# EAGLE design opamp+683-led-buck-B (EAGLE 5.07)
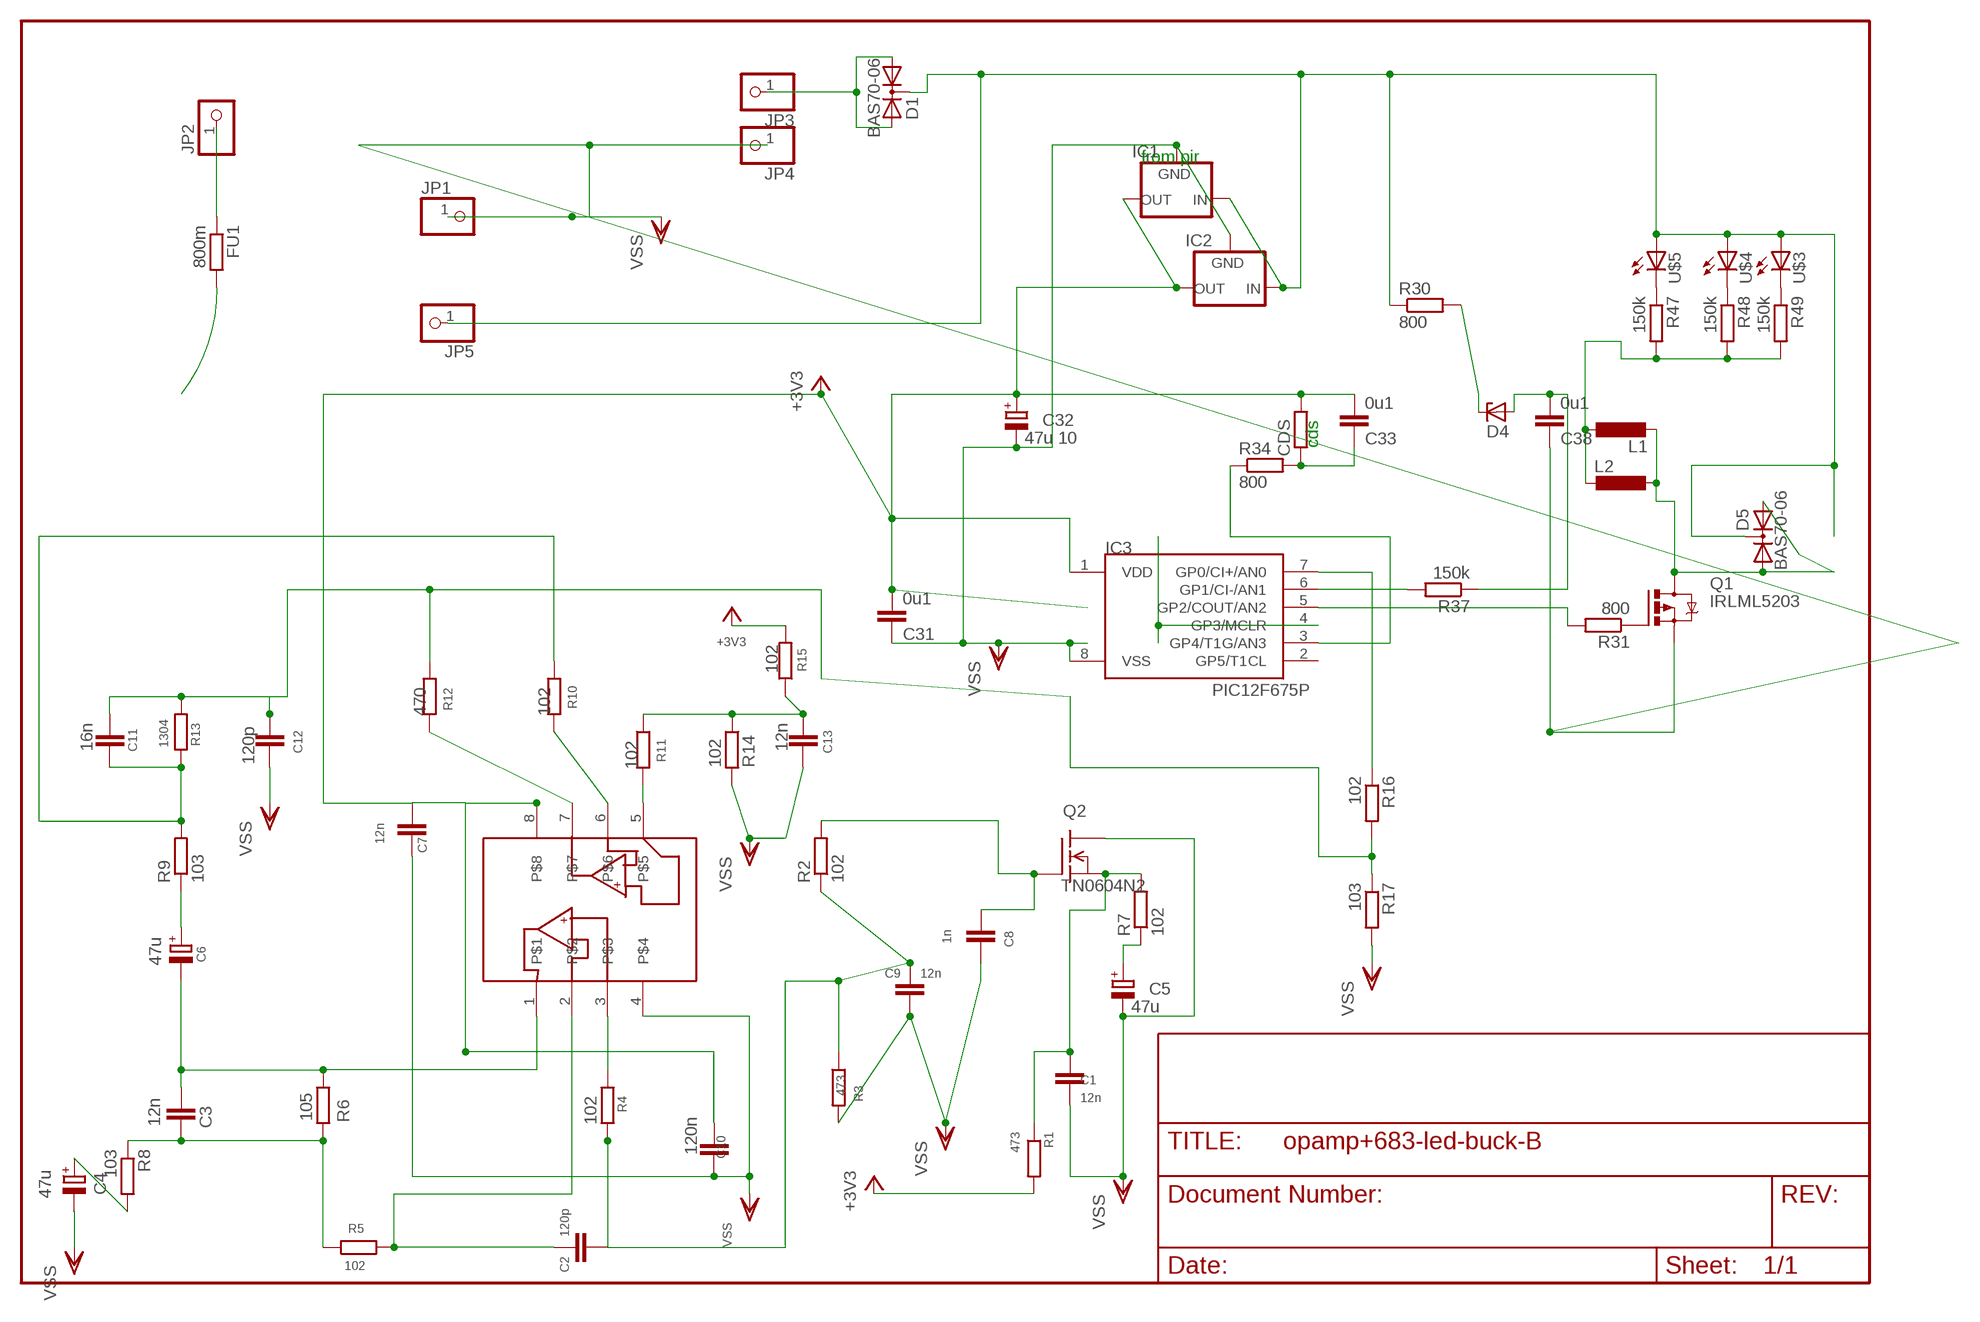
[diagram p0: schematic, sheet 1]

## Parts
C1  12n  C-EUC0805  [C0805]
C2  120p  C-EUC0805  [C0805]
C3  12n  C-EUC0805  [C0805]
C4  47u  CPOL-EUE2.5-5  [E2,5-5]
C5  47u  CPOL-EUE2.5-5  [E2,5-5]
C6  47u  CPOL-EUE2.5-5  [E2,5-5]
C7  12n  C-EUC0805  [C0805]
C8  1n  C-EUC0805  [C0805]
C9  12n  C-EUC0805  [C0805]
C10  120n  C-EUC0805  [C0805]
C11  16n  C-EUC0805  [C0805]
C12  120p  C-EUC0805  [C0805]
C13  12n  C-EUC0805  [C0805]
C31  0u1  C-EUC1206  [C1206]
C32  47u 10  CPOL-EUE2.5-5  [E2,5-5]
C33  0u1  C-EUC1206  [C1206]
C38  0u1  C-EUC0805  [C0805]
CDS  R-EU_0207/5V  [0207/5V]
D1  BAS70-06  [SOT23]
D4  ZENER-DIODESOT23  [SOT23]
D5  BAS70-06  [SOT23]
FU1  800m  R-EU_0204/5  [0204/5]
IC1  XC63FPT  [TO92]
IC2  XC63FPP  [SOT89R]
IC3  PIC12F675P  [DIL8]
JP1  PINHD-1X1  [1X01]
JP2  PINHD-1X1  [1X01]
JP3  PINHD-1X1  [1X01]
JP4  PINHD-1X1  [1X01]
JP5  PINHD-1X1  [1X01]
L1  L-EUL5650M  [L5650M]
L2  L-EU0207/7  [0207/7]
Q1  IRLML5203  [MICRO3]
Q2  TN0604N2  [TO-39]
R1  473  R-EU_R0805  [R0805]
R2  102  R-EU_R0805  [R0805]
R3  473  R-EU_R0805  [R0805]
R4  102  R-EU_R0805  [R0805]
R5  102  R-EU_R0805  [R0805]
R6  105  R-EU_R0805  [R0805]
R7  102  R-EU_R0805  [R0805]
R8  103  R-EU_R0805  [R0805]
R9  103  R-EU_R0805  [R0805]
R10  102  R-EU_R0805  [R0805]
R11  102  R-EU_R0805  [R0805]
R12  470  R-EU_R0805  [R0805]
R13  1304  R-EU_R0805  [R0805]
R14  102  R-EU_R0805  [R0805]
R15  102  R-EU_R0805  [R0805]
R16  102  R-EU_R0805  [R0805]
R17  103  R-EU_R1206  [R1206]
R30  800  R-EU_R0805  [R0805]
R31  800  R-EU_R0805  [R0805]
R34  800  R-EU_0617/22  [0617/22]
R37  150k  R-EU_0207/12  [0207/12]
R47  150k  R-EU_R1206  [R1206]
R48  150k  R-EU_R1206  [R1206]
R49  150k  R-EU_R1206  [R1206]
U$1  MCP6042SOIC  [SO-08]
U$3  LED5MM  [LED5MM]
U$4  LED5MM  [LED5MM]
U$5  LED5MM  [LED5MM]

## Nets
+3V3: C7.1 C10.1 C31.2 C32.+ C33.2 CDS.2 IC1.3(OUT) IC2.3(OUT) IC3.1(VDD) R1.2 R15.2 U$1.8
N$1: D1.1(A1) D1.2(A2) JP3.1
N$4: FU1.1 JP2.1
N$6: D4.3(C) R30.2
N$7: D1.3(C) D5.3(C) IC1.2(IN) IC2.2(IN) JP5.1 R30.1 U$3.A U$4.A U$5.A
N$9: FU1.2
N$10: Q1.1(G) R31.1
N$11: C5.+ R7.1
N$12: IC3.4(GP3/MCLR)
N$13: IC3.6(GP1/CI-/AN1) R37.2
N$14: IC3.5(GP2/COUT/AN2) R31.2
N$19: R4.1 U$1.3
N$21: IC3.3(GP4/T1G/AN3) R34.1
N$22: L1.1 L2.2 R47.2 R48.2 R49.2
N$23: C33.1 CDS.1 R34.2
N$24: C2.1 R5.2 U$1.2
N$25: C3.2 R5.1 R6.2 R8.1
N$26: D5.1(A1) D5.2(A2) L1.2 L2.1 Q1.3(D)
N$27: C4.+ R8.2
N$28: C11.2 R9.2 R10.1 R13.2
N$29: IC3.7(GP0/CI+/AN0) R16.1
N$30: C3.1 C6.- R6.1 U$1.1
N$31: R10.2 U$1.6
N$32: C11.1 C12.2 R12.1 R13.1 R16.2 R17.1
N$34: C38.2 D4.1(A) R37.1
N$35: C6.+ R9.1
N$36: R12.2 U$1.7
N$38: R47.1 U$5.K(C)
N$39: R11.2 U$1.5
N$40: C13.1 R11.1 R14.1 R15.1
N$42: C1.1 Q2.1(S) R1.1 R7.2
N$46: C8.1 Q2.2(G) R2.2
N$52: C2.2 C9.1 R2.1 R3.1 R4.2
N$54: R48.1 U$4.K(C)
N$55: R49.1 U$3.K(C)
VSS: C1.2 C4.- C5.- C7.2 C8.2 C9.2 C10.2 C12.1 C13.2 C31.1 C32.- C38.1 IC1.1(GND) IC2.1(GND) IC3.8(VSS) JP1.1 JP4.1 Q1.2(S) Q2.3(D) R3.2 R14.2 R17.2 U$1.4
Unconnected: IC3.2(GP5/T1CL)

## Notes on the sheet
- from pir
- cds

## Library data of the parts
C1-C3 C7-C13 = rcl-2:C-EU: CAPACITOR, European symbol
C4-C6 C32 = rcl:CPOL-EU: POLARIZED CAPACITOR, European symbol
C31 C33 C38 = rcl:C-EU: CAPACITOR, European symbol
CDS = rcl(2):R-EU_: RESISTOR, European symbol
D1 D5 = diode-1:BAS70-06: Silicon Schottky Diodes General-purpose diode for high-speed switching
D4 = diode-1:ZENER-DIODE: Z-Diode
FU1 R30 R31 R34 R37 R47-R49 = rcl:R-EU_: RESISTOR, European symbol
IC1 IC2 = v-reg:XC63FP: Positiv Voltage Regulators www.torex.co.jp/english/product/pro02/pdf/0201_xc62fp.pdf
IC3 = microchip-3:PIC12F6*: uPC nW 1k Program Flash memory 2x Timer Comparator 10b A/D converter/ 4xIN
JP1-JP5 = pinhead:PINHD-1X1: PIN HEADER
L1 = rcl-2:L-EU: INDUCTOR, European symbol
L2 = rcl:L-EU: INDUCTOR, European symbol
Q1 = transistor-power:IRLML5203: HEXFET P-Channel Power MOSFET
Q2 = transistor-fet:TN0604N2: N-Channel Enhancement MOSFET 40V; 4A; 0,85Ohm
R1-R17 = rcl-2:R-EU_: RESISTOR, European symbol
U$1 = microchip-3:MCP6042
U$3-U$5 = led(3):LED: LED

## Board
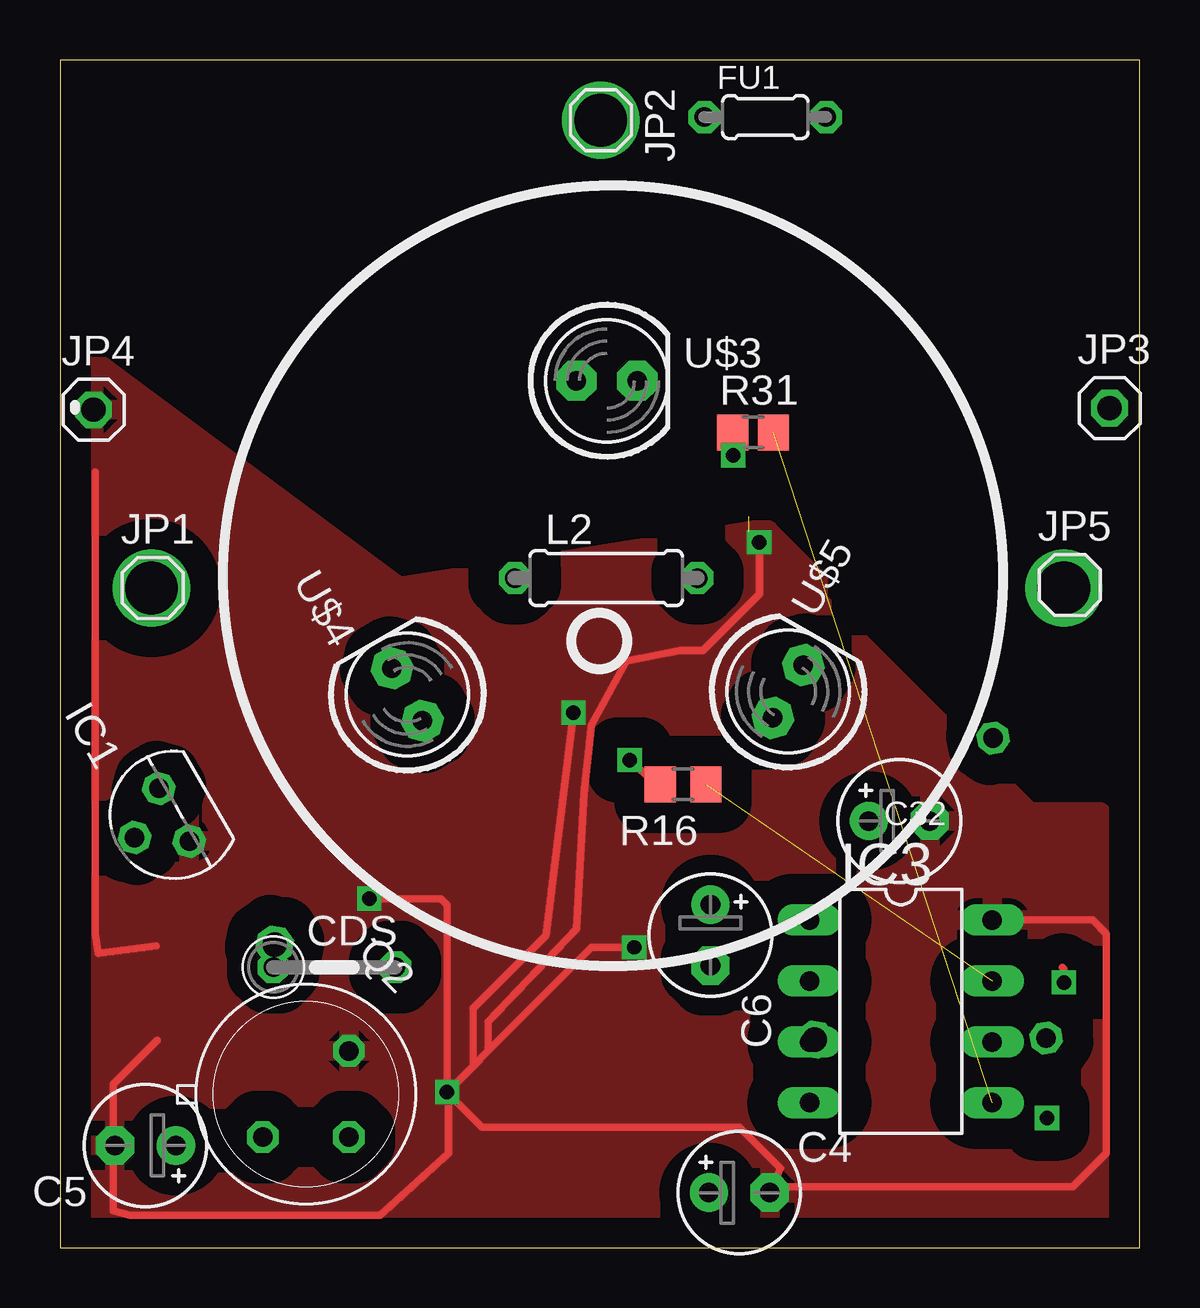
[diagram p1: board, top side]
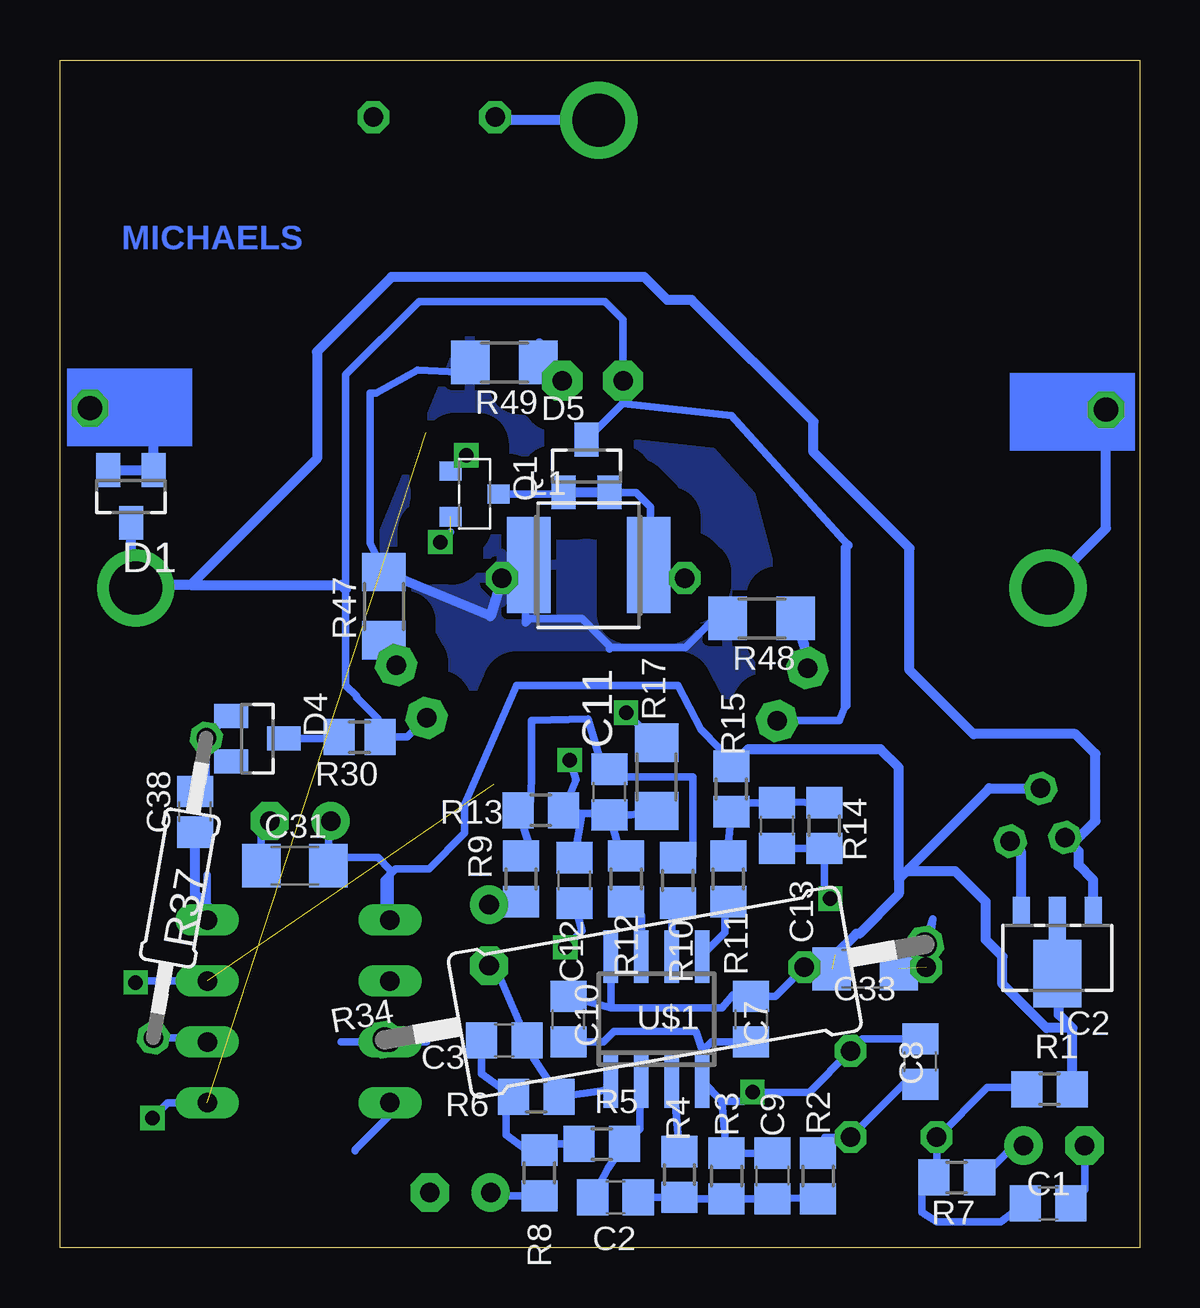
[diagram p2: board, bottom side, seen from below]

Size 45 x 49.5 mm. Coordinates in mm from the lower left corner, seen from the top.
Outline: 0,0 45,0 45,49.5 0,49.5 0,0
Copper layers (1*16): Top 0.035mm / dielectric 1.5mm / Bottom 0.035mm
Design rules "default": minimum track width 10mil, minimum drill 24mil, track to track 8mil, track to pad 8mil, pad to pad 8mil, via to via 8mil, smd to smd 8mil, copper to edge 40mil, drill to drill 8mil, minimum pad ring 10mil, minimum via ring 8mil, stop-mask expansion 4mil, vias tented up to drill 0mil, thermal gap 10mil

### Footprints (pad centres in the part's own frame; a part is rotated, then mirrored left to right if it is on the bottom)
C0805 = smd 1.3 x 1.5: 1 -0.95,0; 2 0.95,0
E2,5-5 = drill 0.813 pad 1.6 round: + -1.27,0 | drill 0.813 pad 1.6 octagon: - 1.27,0
C1206 = smd 1.6 x 1.8: 1 -1.4,0; 2 1.4,0
C0805' = smd 1.3 x 1.5: 1 -0.85,0; 2 0.85,0
0207/5V = drill 0.813 octagon: 1 -2.54,0; 2 2.54,0
SOT23 = smd 1 x 1.4: 1 -0.95,-1.1; 2 0.95,-1.1; 3 0,1.1
0204/5 = drill 0.813 octagon: 1 -2.54,0; 2 2.54,0
TO92 = drill 0.813 octagon: 1 -1.27,0; 2 0,1.905; 3 1.27,0
SOT89R = smd 0.7 x 1.1: 1 1.5,-1.75; 2 -1.5,-1.75 | smd 0.7 x 1.8: 3 0,-1.4 | smd 2 x 2.8: 4 0,0.9
DIL8 = drill 0.813 long: 1 -3.81,-3.81; 2 -1.27,-3.81; 3 1.27,-3.81; 4 3.81,-3.81; 5 3.81,3.81; 6 1.27,3.81; 7 -1.27,3.81; 8 -3.81,3.81
1X01 = drill 1.016 octagon: 1 0,0
L5650M = smd 1.8 x 4: 1 -2.5,0; 2 2.5,0
0207/7 = drill 0.813 octagon: 1 -3.81,0; 2 3.81,0
MICRO3 = smd 0.8 x 0.9: 1 -0.95,-1; 2 0.95,-1; 3 0,1
TO-39 = drill 0.813 octagon: 1 0,-2.54; 2 2.54,0; 3 0,2.54
R0805 = smd 1.3 x 1.5: 1 -0.95,0; 2 0.95,0
R1206 = smd 1.6 x 1.803: 1 -1.422,0; 2 1.422,0
R0805' = smd 1.3 x 1.5: 1 -0.85,0; 2 0.85,0
0617/22 = drill 1.016 octagon: 1 -11.43,0; 2 11.43,0
0207/12 = drill 0.813 octagon: 1 -6.35,0; 2 6.35,0
SO-08 = smd 0.6 x 2.2: 1 -1.905,-2.6; 2 -0.635,-2.6; 3 0.635,-2.6; 4 1.905,-2.6; 5 1.905,2.6; 6 0.635,2.6; 7 -0.635,2.6; 8 -1.905,2.6
LED5MM = drill 0.813 pad 1.676 octagon: A -1.27,0; K 1.27,0

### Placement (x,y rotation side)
C1  3.81,1.84 0 bottom
C2  21.84,2.1 0 bottom
C3  26.48,8.64 180 bottom
C4  28.32,2.29 0 top
C5  3.56,4.25 180 top
C6  27.11,13.02 270 top
C7  16.19,9.53 270 bottom
C8  9.14,7.75 90 bottom
C9  15.3,2.98 90 bottom
C10  23.81,9.53 270 bottom
C11  22.1,18.99 90 bottom
C12  23.56,15.3 90 bottom
C13  15.11,17.59 270 bottom
C31  35.21,15.92 0 bottom
C32  34.99,17.78 0 top
C33  11.43,11.62 180 bottom
C38  0u1  [C0805']  39.37,18.16 90 bottom
CDS  11.43,11.68 0 top
D1  42.04,31.31 180 bottom
D4  36.77,21.21 270 bottom
D5  23.05,32.58 0 bottom
FU1  29.4,47.12 0 top
IC1  4.76,18.04 120 top
IC2  3.43,12.32 180 bottom
IC3  35.05,9.84 270 top
JP1  3.87,27.5 0 top
JP2  22.54,46.99 270 top
JP3  43.75,34.99 0 top
JP4  1.4,34.92 0 top
JP5  42.1,27.62 0 top
L1  22.96,28.44 0 bottom
L2  22.77,27.91 0 top
Q1  27.72,31.41 270 bottom
Q2  10.25,6.4 315 top
R1  3.75,6.6 0 bottom
R2  13.4,2.98 90 bottom
R3  17.21,2.98 90 bottom
R4  19.18,3.05 270 bottom
R5  22.42,4.32 0 bottom
R6  25.15,6.29 180 bottom
R7  7.62,2.92 180 bottom
R8  25.02,3.11 270 bottom
R9  25.78,15.37 90 bottom
R10  19.24,15.3 270 bottom
R11  17.14,15.37 270 bottom
R12  21.4,15.37 270 bottom
R13  24.96,18.22 180 bottom
R14  13.14,17.59 270 bottom
R15  17.02,19.11 90 bottom
R16  25.97,19.3 180 top
R17  20.13,19.62 90 bottom
R30  800  [R0805']  32.51,21.27 180 bottom
R31  800  [R0805']  28.89,33.97 0 top
R34  20.2,10.64 10 bottom
R37  40.01,14.99 260 bottom
R47  31.5,26.73 90 bottom
R48  15.75,26.23 180 bottom
R49  26.48,36.89 180 bottom
U$1  20.13,9.53 0 bottom
U$3  22.8,36.13 0 top
U$4  14.48,23.05 120 top
U$5  30.35,23.18 60 top

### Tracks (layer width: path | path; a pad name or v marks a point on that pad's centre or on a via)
+3V3  (1 unrouted)
  Bottom 0.305: 22.04,10 17.4,10 16.96,10.54 C7.1 15.18,10.47 CDS.2 | 22.04,10 C10.1 | 22.04,10 U$1.8 | C32.+ 33.81,17.69 C31.2 33.47,16.26 31.75,16.26 31.24,15.75 IC3.1 31.5,13.91 31.5,15.3 31.01,15.79 29.62,15.79 28.13,17.27 28.13,18.48 25.97,23.43 19.24,23.43 18.29,21.59 17.53,20.83 R15.2
  Bottom 0.406: R1.2 2.8,9.15 | 2.8,9.15 3.37,9.72 3.37,13.65 IC2.3 | IC1.3 6.26,19.14 9.68,15.72 | 9.68,15.72 10.03,15.37 | 10.03,15.37 10.03,14.73 11.68,13.08 11.81,13.08 12.7,12.19 13.46,12.19 CDS.2 | 10.03,15.37 10.03,20 10.79,20.77 16.32,20.77 R15.2 | 2.8,9.15 3.88,9.15 5.71,10.99 5.71,12.13 6.41,12.83 6.41,14.41 7.68,15.68 9.65,15.68 9.68,15.72
N$1
  Bottom 0.406: JP3.1 43.62,34.86 42.48,34.86 41.09,33.47 D1.1 D1.2
N$2  (via drill 2.2)
  other vias: 3.81,27.5
N$3  (via drill 2.2)
  other vias: 41.85,27.5
N$4
  Bottom 0.406: JP2.1 26.73,46.99 FU1.1
N$5  (via drill 2.2)
  other vias: 22.54,46.99
N$6
  Bottom 0.305: D4.3 33.42,21.21 R30.2
N$7
  Bottom 0.305: U$4.A 15.09,21.97 12.51,21.97 12.26,22.6 | U$5.A 30.52,21.27 R30.1 31.75,21.36 31.75,22.04 32.64,22.92 32.64,22.99 33.08,23.43 33.08,27.43 33.08,36.39 30.04,39.43 22.29,39.43 21.53,38.67 U$3.A | U$3.A 21.53,35.2 D5.3 | U$3.A 21.53,35.18 17.02,34.67 12.16,29.27
  Bottom 0.406: IC2.2 1.93,15.33 2.54,15.94 2.54,16.52 IC1.2 2.54,17.09 1.84,17.78 1.84,20.57 2.67,21.4 6.92,21.4 9.59,24.07 9.59,29.15 13.59,33.15 13.59,34.42 18.67,39.5 19.68,39.5 20.64,40.45 31.18,40.45 34.29,37.34 34.29,32.89 39.56,27.62 | 39.56,27.62 33.27,27.62 33.08,27.43 | 39.56,27.62 JP5.1 42.04,27.69 D1.3 | 12.26,22.6 12.26,29.18 12.16,29.27
N$10  (via drill 0.6)
  Top 0.305: v28.06,33.02 R31.1
  Bottom 0.305: Q1.1 v28.06,33.02
N$11
  Bottom 0.305: R7.1 6.92,2.54 5.33,4.13 4.95,4.13 C5.+
N$12
  Bottom 0.305: IC3.4 31.24,5.52 32.7,4.06 32.7,4.03
N$13
  Bottom 0.305: R37.2 39.02,8.73 IC3.6
N$14  (via drill 0.6)  (1 unrouted)
  Top 0.305: v41.15,5.4 41.15,5.65
  Bottom 0.305: 39.12,6.03 IC3.5 40.51,6.03 v41.15,5.4
N$19
  Bottom 0.305: U$1.3 19.43,6.92 R4.1
N$21
  Bottom 0.305: 33.27,8.57 IC3.3 29.72,8.57 R34.1
N$22
  Bottom 0.305: R49.2 28.36,36.49 30.1,36.58 31.81,35.62 32.07,35.62 32.07,29.36 R47.2 | R48.2 17.72,26.23 18.92,25.02 22.04,25.02 22.1,24.96 22.1,25.08 23.24,26.23 25.4,26.23 25.59,26.04 25.59,28.31 L1.1
  Bottom 0.406: R47.2 27.05,26.32 L2.2 26.23,28.25 L1.1
  pour Bottom (isolate 1.27, rank 2): 21.97,38.29 28.07,38.23 36.45,17.72 12.57,17.65 17.97,37.97 21.59,38.23
N$23  (1 unrouted)
  Bottom 0.305: R34.2 8.61,13.69 CDS.1
N$24
  Bottom 0.305: U$1.2 20.83,6.92 20.83,4.96 R5.2 22.16,3.3 C2.1
N$25
  Bottom 0.305: R5.1 24.76,4.32 R8.1 25.52,4.06 26.42,4.7 26.42,5.78 R6.2 27.43,7.24 C3.2
N$26
  Bottom 0.305: Q1.3 24.07,31.41 D5.1 | D5.2 21,31.48 20.38,30.86 20.38,28.51 L1.2
  Bottom 0.406: D5.2 D5.1 | L2.1 20.18,27.91 L1.2
N$27
  Bottom 0.305: R8.2 27.05,2.16 C4.+
N$28
  Bottom 0.305: R10.1 18.61,16.32 18.61,19.62 21.33,19.62 C11.2 22.35,19.87 22.99,22.04 25.34,21.97 25.34,19.49 25.4,18.35 R13.2 25.4,16.7 R9.2
N$29  (via drill 0.6)  (1 unrouted)
  Top 0.305: v41.85,11.05 41.85,11.62 41.78,11.68
  Bottom 0.305: 41.59,11.18 41.53,11.11 IC3.7 41.78,11.11 v41.85,11.05
N$30
  Bottom 0.305: U$1.1 22.29,6.54 R6.1 25.28,7.94 C3.1 26.67,11.31 C6.-
N$31
  Bottom 0.305: U$1.6 19.49,14.23 R10.2
N$32  (via drill 0.6)
  Top 0.305: v23.75,20.32 24.39,19.75 R16.2
  Bottom 0.305: 23.24,18.09 C12.2 | 23.24,18.09 R13.1 23.5,19.5 v23.75,20.32 | 23.24,18.09 21.84,18.09 C11.1 | C11.1 21.72,16.7 R12.1 | R17.1 21.21,18.04 C11.1
N$34
  Bottom 0.305: D4.1 37.98,22.16 R37.1 38.9,19.48 C38.2
N$35
  Bottom 0.305: R9.1 26.98,14.42 C6.+
N$36
  Bottom 0.305: U$1.7 20.77,13.85 R12.2
N$38
  Bottom 0.406: U$5.K 31.3,24.7 R47.1
N$39
  Bottom 0.305: U$1.5 18.22,12.19 17.27,13.14 17.27,14.35 R11.2
N$40
  Bottom 0.305: R14.1 15.56,18.6 C13.1 17.34,18.54 R15.1 17.14,16.89 R11.1
N$42
  Bottom 0.305: C1.1 5.78,1.08 8.45,1.08 9.08,1.46 9.08,2.35 R7.2 8.45,2.97 Q2.1 8.41,4.6 6.35,6.67 4.76,6.67 R1.1
N$46
  Bottom 0.305: C8.1 9.85,6.8 Q2.2 13.11,4.6 R2.2
N$52
  Bottom 0.305: R2.1 15.62,2.1 C9.1 R3.1 19.37,2.03 R4.2 21.34,2.1 C2.2
N$54
  Bottom 0.406: U$4.K 13.97,25.11 R48.1
N$55
  Bottom 0.406: U$3.K 25.02,37.69 R49.1
VSS  (via drill 0.6)  (1 unrouted)
  Top 0.305: v23.94,12.51 22.16,12.51 17.84,8.19 | v16.13,6.48 17.59,5.02 28.32,5.02 30.04,3.3 C4.- 30.1,2.54 42.23,2.54 43.62,3.94 43.62,13.08 43.05,13.65 IC3.8 | 4.06,8.63 2.22,6.79 2.22,4.19 | v16.13,6.48 16.19,6.41 16.19,3.93 13.34,1.33 2.92,1.33 2.22,1.52 2.22,4.19 | 2.22,4.19 C5.- | 1.46,32.32 1.46,13.08 1.59,12.26 4,12.57 | v12.89,14.54 15.88,14.54 16.13,14.29 v16.13,6.48 | v21.4,22.29 20.26,13.02 17.21,9.97 17.21,7.56 | v16.13,6.48 17.21,7.56 | v29.15,29.4 29.15,27.24 26.8,24.89 25.84,24.89 23.62,24.45 22.16,21.78 21.84,18.92 21.53,13.27 17.84,9.4 17.84,8.19 | 17.21,7.56 17.84,8.19
  Bottom 0.305: C7.2 17.84,8.57 18.22,8.19 | 18.22,8.19 18.22,7.62 18.29,7.56 18.29,6.99 U$1.4 17.4,6.1 | C10.2 22.35,8.57 21.91,9.02 18.48,9.02 18.22,8.19 | 17.4,6.1 R3.2 C9.2 | C12.1 23.24,13.21 v23.94,12.51 | C13.2 R14.2 13.14,14.8 v12.89,14.54 | 17.4,6.1 16.51,6.1 v16.13,6.48 13.77,6.48 Q2.3 11.54,8.7 C8.2 | C5.- 2.29,2.42 C1.2 | R17.2 19.94,20.89 v21.4,22.29 | 38.92,13.59 IC3.8 38.86,14.22 38.86,15.53 | 36.68,15.85 C31.1 36.61,17.43 C32.- | v29.15,29.4 28.72,29.83
  Bottom 0.406: IC2.1 4.93,16.47 IC1.1 | JP4.1 1.4,29.97 JP1.1 | C38.1 39.37,14.73 38.86,14.22
  pour Top (isolate 1.27): 1.14,37.21 14.16,27.56 28.96,29.91 29.53,29.91 31.62,27.81 31.62,26.99 40.45,18.16 43.37,18.16 43.81,17.72 43.81,0.76 43.56,0.51 0.76,0.51 0.19,1.08
(copper drawn outside any net)
  shapes: Bottom area x2

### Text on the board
Bottom: MICHAELS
